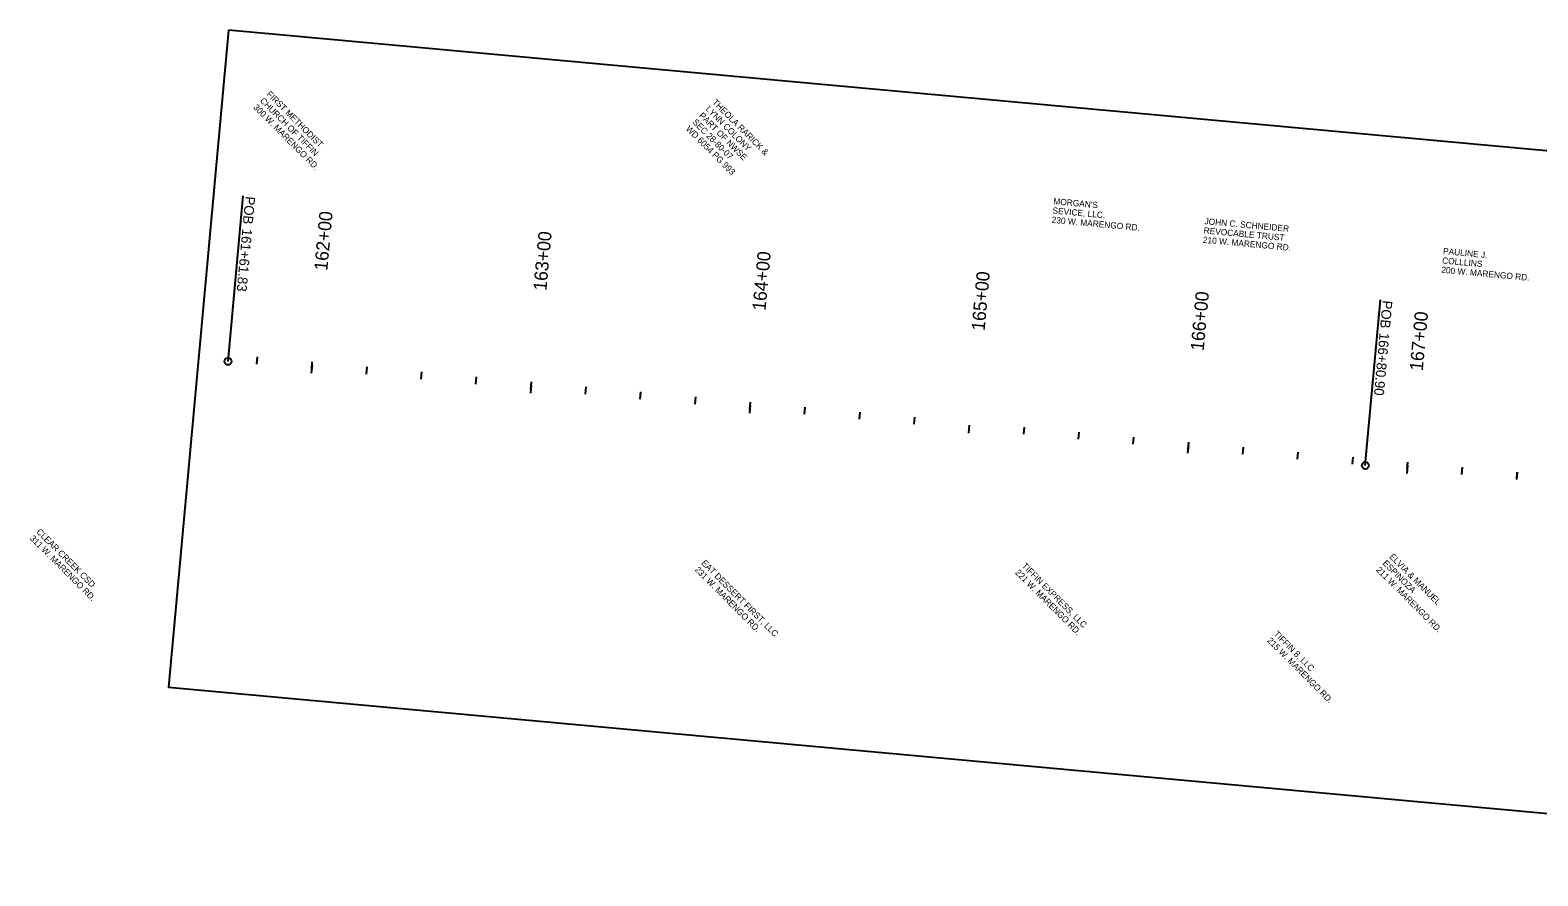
# Model space of a CAD drawing. Extents: x 20499788 to 20505371, y 7953467 to 7954209.
# Drawn here: x 20499788 to 20500473, y 7953824 to 7954209 of the extents above; entities that cross this region are included whole.
import ezdxf

# ---------------------------------------------------------------- set-up
doc = ezdxf.new("R2010")
doc.units = 0
for name, color, linetype in [('NamedBoundary', 7, 'Continuous'), ('Text', 7, 'Continuous'), ('TextAlignment', 7, 'Continuous'), ('TextAlignmentLrg', 7, 'Continuous'), ('TextAlignmentSml', 7, 'Continuous')]:
    doc.layers.add(name, color=color, linetype=linetype)

msp = doc.modelspace()

# ---------------------------------------------------------------- linework, layer by layer
at = {"layer": 'NamedBoundary'}
msp.add_lwpolyline([(20499877.7, 7954208.56), (20499850.36, 7953909.81), (20500786.95, 7953824.1), (20500814.29, 7954122.85)], close=True, dxfattribs=at)
at = {"layer": 'TextAlignment'}
for p, q in [((20499877.47, 7954057.95), (20499884.36, 7954133.24)), ((20499884.36, 7954133.24), (20499884.36, 7954133.24)), ((20500394.39, 7954010.65), (20500401.27, 7954085.94)), ((20500401.27, 7954085.94), (20500401.27, 7954085.94))]:
    msp.add_line(p, q, dxfattribs=at)
for centre in [(20499877.47, 7954057.95), (20500394.39, 7954010.65)]:
    msp.add_circle(centre, 1.6, dxfattribs=at)
at = {"layer": 'TextAlignmentLrg'}
for p, q in [((20499915.49, 7954054.48), (20499915.78, 7954057.74)), ((20500015.07, 7954045.36), (20500015.37, 7954048.63)), ((20500114.65, 7954036.25), (20500114.95, 7954039.51)), ((20500214.4, 7954028.97), (20500214.07, 7954025.31)), ((20500313.82, 7954018.02), (20500314.12, 7954021.29)), ((20500413.4, 7954008.91), (20500413.7, 7954012.17)), ((20500413.4, 7954008.91), (20500413.7, 7954012.17))]:
    msp.add_line(p, q, dxfattribs=at)
at = {"layer": 'TextAlignmentSml'}
for p, q in [((20499890.59, 7954056.75), (20499890.89, 7954060.02)), ((20499915.65, 7954056.3), (20499915.32, 7954052.65)), ((20499940.38, 7954052.2), (20499940.68, 7954055.46)), ((20499965.28, 7954049.92), (20499965.58, 7954053.18)), ((20499990.17, 7954047.64), (20499990.47, 7954050.9)), ((20500015.24, 7954047.19), (20500014.9, 7954043.53)), ((20500039.97, 7954043.09), (20500040.26, 7954046.35)), ((20500064.86, 7954040.81), (20500065.16, 7954044.07)), ((20500089.76, 7954038.53), (20500090.06, 7954041.79)), ((20500114.82, 7954038.08), (20500114.49, 7954034.42)), ((20500139.55, 7954033.97), (20500139.85, 7954037.23)), ((20500164.45, 7954031.69), (20500164.74, 7954034.96)), ((20500189.34, 7954029.42), (20500189.64, 7954032.68)), ((20500214.4, 7954028.97), (20500214.07, 7954025.31)), ((20500239.13, 7954024.86), (20500239.43, 7954028.12)), ((20500264.03, 7954022.58), (20500264.33, 7954025.84)), ((20500288.93, 7954020.3), (20500289.22, 7954023.57)), ((20500313.99, 7954019.85), (20500313.65, 7954016.2)), ((20500338.72, 7954015.75), (20500339.02, 7954019.01)), ((20500363.61, 7954013.47), (20500363.91, 7954016.73)), ((20500388.51, 7954011.19), (20500388.81, 7954014.45)), ((20500413.57, 7954010.74), (20500413.24, 7954007.08)), ((20500413.57, 7954010.74), (20500413.24, 7954007.08)), ((20500438.3, 7954006.63), (20500438.6, 7954009.9)), ((20500438.3, 7954006.63), (20500438.6, 7954009.9)), ((20500463.2, 7954004.36), (20500463.49, 7954007.62)), ((20500463.2, 7954004.36), (20500463.5, 7954007.62))]:
    msp.add_line(p, q, dxfattribs=at)

# ---------------------------------------------------------------- texts
at = {"layer": 'Text'}
for s, height, rotation, p in [('CHURCH OF TIFFIN', 2.8346, 314.98356, (20499891.74, 7954176.22)), ('FIRST METHODIST', 2.8346, 314.98356, (20499894.75, 7954179.22)), ('THEOLA RARICK &', 2.8346, 314.98356, (20500097.36, 7954175.49)), ('300 W. MARENGO RD.', 2.8346, 314.98356, (20499888.73, 7954173.21)), ('PART OF NWSE', 2.8346, 314.98356, (20500091.34, 7954169.48)), ('LYNN COLONY', 2.8346, 314.98356, (20500094.35, 7954172.48)), ('WD 6054 PG 993', 2.8346, 314.98356, (20500085.33, 7954163.46)), ('SEC 28-80-07', 2.8346, 314.98356, (20500088.34, 7954166.47)), ("MORGAN'S ", 2.835, 354.76449, (20500252.51, 7954129.44)), ('230 W. MARENGO RD.', 2.8346, 354.76449, (20500251.73, 7954120.98)), ('SEVICE, LLC.', 2.8346, 354.76449, (20500252.12, 7954125.21)), ('JOHN C. SCHNEIDER', 2.8346, 354.76449, (20500321.22, 7954120.38)), ('REVOCABLE TRUST', 2.8346, 354.76449, (20500320.83, 7954116.15)), ('210 W. MARENGO RD.', 2.8346, 354.76449, (20500320.44, 7954111.91)), ('PAULINE J.', 2.835, 354.76449, (20500429.62, 7954106.73)), ('COLLLINS', 2.835, 354.76449, (20500429.23, 7954102.5)), ('200 W. MARENGO RD.', 2.8346, 354.76449, (20500428.84, 7954098.27)), ('311 W. MARENGO RD.', 2.8346, 314.98356, (20499787.15, 7953977.26)), ('CLEAR CREEK CSD', 2.8346, 314.98356, (20499790.15, 7953980.27)), ('EAT DESSERT FIRST, LLC', 2.8346, 314.98356, (20500092.37, 7953966.05)), ('TIFFIN EXPRESS, LLC', 2.8346, 314.98356, (20500238.05, 7953964.74)), ('ESPINOZA', 2.835, 314.98356, (20500402.08, 7953965.96)), ('ELVIA & MANUEL', 2.8346, 314.98356, (20500405.09, 7953968.96)), ('231 W. MARENGO RD.', 2.8346, 314.98356, (20500089.37, 7953963.04)), ('221 W. MARENGO RD.', 2.8346, 314.98356, (20500235.04, 7953961.74)), ('211 W. MARENGO RD.', 2.8346, 314.98356, (20500399.08, 7953962.95)), ('215 W. MARENGO RD.', 2.8346, 314.98356, (20500349.55, 7953930.78)), ('TIFFIN 8, LLC', 2.8346, 314.98356, (20500352.56, 7953933.79))]:
    msp.add_text(s, height=height, rotation=rotation, dxfattribs=at).set_placement(p)
at = {"layer": 'TextAlignment'}
for s, p in [('POB ', (20499885.35, 7954133.15)), ('161+61.83', (20499884, 7954118.43)), ('POB ', (20500402.26, 7954085.85)), ('166+80.90', (20500400.91, 7954071.12))]:
    msp.add_text(s, height=4.5, rotation=264.77145, dxfattribs=at).set_placement(p)
at = {"layer": 'TextAlignmentLrg'}
msp.add_text('165+00', height=6.012, rotation=84.77145, dxfattribs=at).set_placement((20500221.33, 7954071.68))
at = {"layer": 'TextAlignmentSml'}
for s, p in [('162+00', (20499922.58, 7954099.02)), ('163+00', (20500022.16, 7954089.9)), ('164+00', (20500121.75, 7954080.79)), ('165+00', (20500221.33, 7954071.68)), ('166+00', (20500320.92, 7954062.56)), ('167+00', (20500420.5, 7954053.45)), ('167+00', (20500420.5, 7954053.45))]:
    msp.add_text(s, height=6.012, rotation=84.77145, dxfattribs=at).set_placement(p)

doc.saveas('drawing.dxf')
